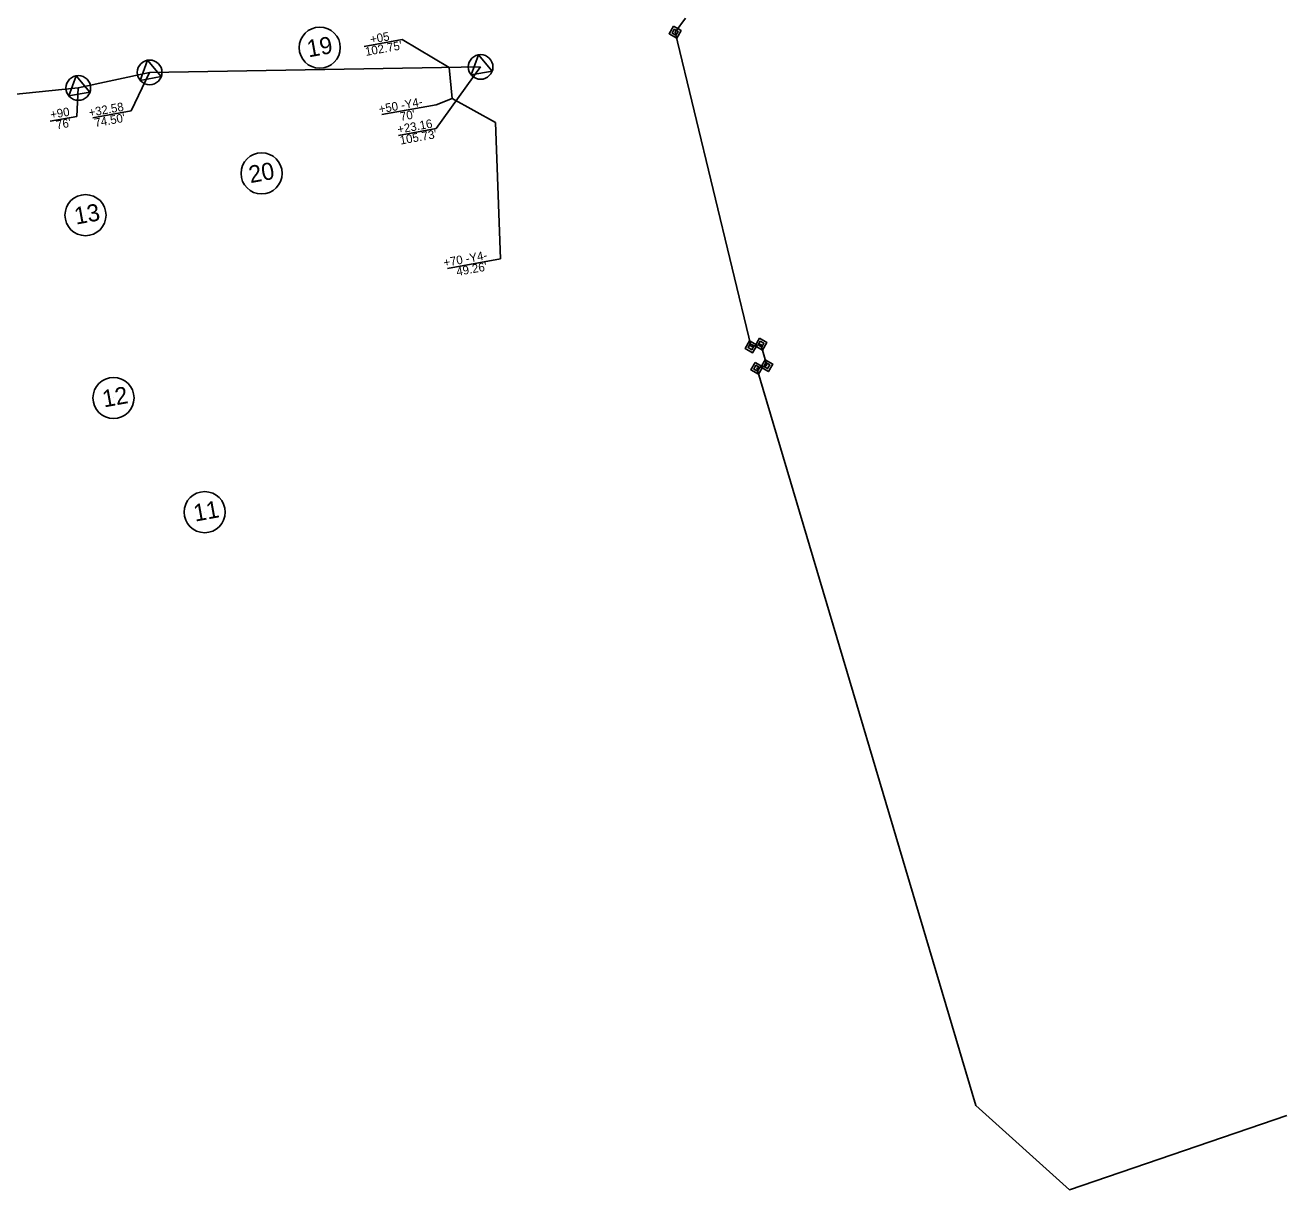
# Model space of a CAD drawing. Extents: x 1618217 to 1621927, y 897445 to 899141.
# Drawn here: x 1621191 to 1621927, y 897445 to 898125 of the extents above; entities that cross this region are included whole.
import ezdxf

# ---------------------------------------------------------------- set-up
doc = ezdxf.new("R2010")
doc.units = 0
for name, color, linetype in [('Prop Easement Permanent Utility', 7, 'Continuous'), ('Prop Easement Temporary Drainage', 7, 'Continuous'), ('Prop Easement Temporary Drainage Station Offsets', 7, 'Continuous'), ('Prop Parcel Number CELL', 7, 'Continuous'), ('Prop ROW Marker CELL', 7, 'Continuous'), ('Prop ROW Permanent Easement CELL', 7, 'Continuous'), ('Prop ROW RW Lines', 7, 'Continuous'), ('Prop ROW Station Offsets', 7, 'Continuous')]:
    doc.layers.add(name, color=color, linetype=linetype)

msp = doc.modelspace()

# ---------------------------------------------------------------- linework, layer by layer
at = {"layer": 'Prop Easement Permanent Utility'}
for p, q in [((1621569.74, 898120.49), (1621575.83, 898128.66)), ((1621614.08, 897937.04), (1621569.74, 898120.49)), ((1621614.08, 897937.04), (1621619.87, 897938.59)), ((1621619.87, 897938.59), (1621623.24, 897926.03)), ((1621617.44, 897924.48), (1621623.24, 897926.03))]:
    msp.add_line(p, q, dxfattribs=at)
msp.add_lwpolyline([(1621617.44, 897924.48), (1621745.17, 897494.4), (1621799.86, 897445.33), (1621926.69, 897488.62)], dxfattribs=at)
at = {"layer": 'Prop Easement Temporary Drainage'}
for q in [(1621437.86, 898099.98), (1621464.91, 898067.86)]:
    msp.add_line((1621439.71, 898081.82), q, dxfattribs=at)
at = {"layer": 'Prop Easement Temporary Drainage Station Offsets'}
for p, q in [((1621388.36, 898112.2), (1621410.55, 898116.22)), ((1621410.55, 898116.22), (1621437.86, 898099.98)), ((1621430.29, 898078.19), (1621439.71, 898081.82)), ((1621398.57, 898072.45), (1621430.29, 898078.19)), ((1621467.83, 897988.38), (1621464.91, 898067.86)), ((1621436.95, 897982.79), (1621467.83, 897988.38))]:
    msp.add_line(p, q, dxfattribs=at)
at = {"layer": 'Prop Parcel Number CELL'}
for p, q in [((1621362.42, 898111.53), (1621362.42, 898111.53)), ((1621328.48, 898038.18), (1621328.48, 898038.18)), ((1621225.71, 898013.81), (1621225.71, 898013.81)), ((1621242.06, 897907.17), (1621242.06, 897907.17)), ((1621295.26, 897840.57), (1621295.26, 897840.57))]:
    msp.add_line(p, q, dxfattribs=at)
for centre in [(1621362.42, 898111.53), (1621328.48, 898038.18), (1621225.71, 898013.81), (1621242.06, 897907.17), (1621295.26, 897840.57)]:
    msp.add_circle(centre, 12, dxfattribs=at)
at = {"layer": 'Prop ROW Marker CELL'}
for p, q in [((1621569.76, 898120.51), (1621569.76, 898120.51)), ((1621263.16, 898097.07), (1621263.16, 898097.07)), ((1621456.26, 898100.28), (1621456.26, 898100.28)), ((1621456.26, 898100.28), (1621456.26, 898100.28)), ((1621221.53, 898088), (1621221.53, 898088)), ((1621614.08, 897937.04), (1621614.08, 897937.04)), ((1621619.87, 897938.59), (1621619.87, 897938.59)), ((1621617.44, 897924.48), (1621617.44, 897924.48)), ((1621623.24, 897926.03), (1621623.24, 897926.03))]:
    msp.add_line(p, q, dxfattribs=at)
for points in [[(1621257.65, 898092.41), (1621261.88, 898104.15), (1621269.96, 898094.64)], [(1621450.75, 898095.63), (1621454.98, 898107.37), (1621463.05, 898097.85)], [(1621450.75, 898095.63), (1621454.98, 898107.37), (1621463.05, 898097.85)], [(1621216.02, 898083.35), (1621220.25, 898095.09), (1621228.32, 898085.57)]]:
    msp.add_lwpolyline(points, close=True, dxfattribs=at)
for centre in [(1621263.16, 898097.07), (1621456.26, 898100.28), (1621456.26, 898100.28), (1621221.53, 898088)]:
    msp.add_circle(centre, 7.2, dxfattribs=at)
at = {"layer": 'Prop ROW Permanent Easement CELL'}
for points in [[(1621568.83, 898123.99), (1621573.23, 898121.45), (1621570.69, 898117.04), (1621566.28, 898119.58)], [(1621569.29, 898122.25), (1621571.49, 898120.98), (1621570.22, 898118.78), (1621568.02, 898120.05)], [(1621613.15, 897940.51), (1621617.56, 897937.97), (1621615.01, 897933.56), (1621610.6, 897936.1)], [(1621618.94, 897942.06), (1621623.35, 897939.52), (1621620.8, 897935.11), (1621616.4, 897937.66)], [(1621619.41, 897940.33), (1621621.61, 897939.05), (1621620.34, 897936.85), (1621618.14, 897938.12)], [(1621613.61, 897938.77), (1621615.82, 897937.5), (1621614.54, 897935.3), (1621612.34, 897936.57)], [(1621616.51, 897927.96), (1621620.92, 897925.41), (1621618.37, 897921), (1621613.96, 897923.55)], [(1621616.97, 897926.22), (1621619.18, 897924.94), (1621617.9, 897922.74), (1621615.7, 897924.01)], [(1621622.31, 897929.51), (1621626.71, 897926.96), (1621624.17, 897922.55), (1621619.76, 897925.1)], [(1621622.77, 897927.77), (1621624.97, 897926.49), (1621623.7, 897924.29), (1621621.5, 897925.56)]]:
    msp.add_lwpolyline(points, close=True, dxfattribs=at)
at = {"layer": 'Prop ROW RW Lines'}
for p, q in [((1621221.53, 898088), (1621263.16, 898097.07)), ((1621263.16, 898097.07), (1621456.26, 898100.28)), ((1621056.89, 898071.23), (1621221.53, 898088))]:
    msp.add_line(p, q, dxfattribs=at)
at = {"layer": 'Prop ROW Station Offsets'}
for p, q in [((1621252.39, 898074.67), (1621263.16, 898097.07)), ((1621430.37, 898064.27), (1621456.26, 898100.28)), ((1621220.69, 898071.4), (1621221.53, 898088)), ((1621229.94, 898070.61), (1621252.39, 898074.67)), ((1621205.14, 898068.58), (1621220.69, 898071.4)), ((1621408.44, 898060.3), (1621430.37, 898064.27))]:
    msp.add_line(p, q, dxfattribs=at)

# ---------------------------------------------------------------- texts
at = {"layer": 'Prop Easement Temporary Drainage Station Offsets'}
for s, p in [('+05', (1621392.28, 898113.81)), ("102.75'", (1621389.37, 898106.68)), ('+50 -Y4-', (1621397.3, 898073.11)), ("70'", (1621409.73, 898068.75)), ('+70 -Y4-', (1621435.04, 897983.57)), ("49.26'", (1621442.6, 897978.33))]:
    msp.add_text(s, height=5, rotation=10.2583, dxfattribs=at).set_placement(p)
at = {"layer": 'Prop Parcel Number CELL'}
for s, p in [('19', (1621355.89, 898105.81)), ('20', (1621321.95, 898032.46)), ('13', (1621220.15, 898008.26)), ('12', (1621236.51, 897901.62)), ('11', (1621289.71, 897835.03))]:
    msp.add_text(s, height=10, rotation=10.2583, dxfattribs=at).set_placement(p)
at = {"layer": 'Prop ROW Station Offsets'}
for s, p in [('+32.58', (1621228.03, 898071.11)), ('+90', (1621205.62, 898069.87)), ("74.50'", (1621231.43, 898065.12)), ("76'", (1621209.03, 898063.88)), ('+23.16', (1621408.16, 898061.29)), ("105.73'", (1621409.6, 898054.95))]:
    msp.add_text(s, height=5, rotation=10.2583, dxfattribs=at).set_placement(p)

doc.saveas('drawing.dxf')
